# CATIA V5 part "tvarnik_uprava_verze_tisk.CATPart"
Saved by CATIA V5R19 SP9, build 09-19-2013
Part number: Part41.1
Bounding box of the stored display mesh (mm): x -57 to 50, y -37 to 37, z -20 to 10.351
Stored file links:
  C:\Users\jsmid\Desktop\DP_Smidak_Forma LEGO\tvarnik_uprava_verze_tisk.CATPart
  C:\Users\jsmid\Desktop\Forma_kostka\Product3.CATProduct
  C:\Users\jsmid\Desktop\DP_Smidak_Forma LEGO\LEGO_kostka.CATPart
  C:\Users\jsmid\Desktop\Forma_kostka\Babyplast_univ_ram_plus_LEGO_2.CATProduct
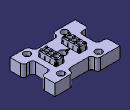
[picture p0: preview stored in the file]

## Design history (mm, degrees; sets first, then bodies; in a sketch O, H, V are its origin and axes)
Set1 "vtok"
  Point1: (0, 0, 0)
  Point2: (0, 0, 40)
  Point3: (0, 0, -7)
  Point4: (6.2, 0, -1.4)
  Point5: (8.8, 0, -0.58)
  Point6: (11.1, 0, -0.58)
  Point7: (-6.2, 0, -1.4)
  Point8: (-8.8, 0, -0.58)
  Point9: (-11.1, 0, -0.58)
  Line1: type PtPt, SecondPoint Point5, FirstPoint Point4
  Line2: type PtPt, SecondPoint Point6, FirstPoint Point5
  Line3: type PtPt, SecondPoint Point8, FirstPoint Point7
  Line4: type PtPt, SecondPoint Point9, FirstPoint Point8
  Point10: (0, 0, -1.4), relative to Point1
  Line5: type PtPt, SecondPoint Point10, FirstPoint Point2
  Line6: type PtPt, SecondPoint Point3, FirstPoint Point10
  Line7: type PtPt, SecondPoint Point7, FirstPoint Point10
  Line8: type PtPt, SecondPoint Point4, FirstPoint Point10
Set2
  DatumSurface1: linked copy from another document
  DatumSurface2: linked copy from another document
Body1 (main body)
  Sketch1 on xy-plane, origin (0, 0, 0), H (1, 0, 0), V (0, 1, 0)
    line L1 (-57, -37) -> (-0.0515, -37)
    line L2 (-0.0515, -37) -> (-0.0515, 37)
    line L3 (-0.0515, 37) -> (-57, 37)
    line L4 (-57, 37) -> (-57, -37)
    length L2 = 74
    distance H L3 = 37
    distance V L4 = 57
    horizontal: L1 H, L3 H
    vertical: L2 V, L4 V
  Pad1: profile Sketch1, direction (0, 0, 1), length 32
  AssyPrtSPLIT1: SplitPlane DatumSurface1
  Sketch2 on xy-plane, origin (0, 0, 0), H (1, 0, 0), V (0, 1, 0)
    line L1 (-0.0515, -37) -> (73, -37)
    line L2 (73, -37) -> (73, 37)
    line L3 (73, 37) -> (-0.0515, 37)
    line L4 (-0.0515, 37) -> (-0.0515, -37)
    length L2 = 74
    distance H L1 = 37
    distance V L2 = 73
    horizontal: L1 H, L3 H
    vertical: L2 V, L4 V
  Pad2: profile Sketch2, direction (0, 0, 1), length 32
  AssyPrtSPLIT2: SplitPlane DatumSurface2
  Sketch3 on xy-plane, origin (0, 0, 0), H (1, 0, 0), V (0, 1, 0)
    line L1 (-57, -37) -> (50, -37)
    line L2 (50, -37) -> (50, 37)
    line L3 (50, 37) -> (-57, 37)
    line L4 (-57, 37) -> (-57, -37)
    length L2 = 74
    distance H L1 = 37
    distance V L2 = 50
    distance L4 V = 57
    horizontal: L1 H, L3 H
    vertical: L2 V, L4 V
  Pad3: profile Sketch3, direction (0, 0, -1), length 20.027
  DatumCurve1 to DatumCurve8
  Sketch4 on start face of Pad3, origin (0, 0, 0), H (1, 0, 0), V (0, 1, 0)
  Sketch5 on face of AssyPrtSPLIT2, origin (0, 0, 8.643), H (1, 0, 0), V (0, 1, 0)
    circle A1 centre (18.939, -8.04) radius 2.25
    reference projected arc E1 centre (18.939, -8.04) radius 2.25 from (18.939, -10.29) to (18.939, -5.79) ccw from edge [start face of Pad3 | face of AssyPrtSPLIT2]
    circle A2 centre (18.939, 0) radius 2.6
    point P2 (18.939, 0)
    circle A3 centre (18.939, 8.04) radius 2.25
    reference projected arc E2 centre (18.939, 8.04) radius 2.25 from (18.939, 5.79) to (18.939, 10.29) ccw from edge [start face of Pad3 | face of AssyPrtSPLIT2]
    circle A4 centre (-18.939, -8.04) radius 2.25
    circle A5 centre (-18.939, 0) radius 2.6
    circle A6 centre (-18.939, 8.04) radius 2.25
    radius A1 = 2.25
    distance E1 A1 = 0
    radius A2 = 2.6
    distance A3 E2 = 0
    radius A3 = 2.25
    coincidence: P2 H
    symmetry: A1 A4 V, A2 A5 V, A3 A6 V
  Pocket1: profile Sketch5, direction (0, 0, -1), up to xy-plane
  Sketch6 on face of AssyPrtSPLIT2, origin (0, 0, 8.643), H (1, 0, 0), V (0, 1, 0)
    circle A1 centre (18.939, -8.04) radius 2.25
    point P1 (18.939, -8.04)
    reference projected arc E1 centre (18.939, -8.04) radius 2.25 from (18.939, -10.29) to (18.939, -5.79) ccw from edge [start face of Pad3 | face of AssyPrtSPLIT2]
    circle A2 centre (18.939, 0) radius 2.25
    point P2 (18.939, 0)
    circle A3 centre (18.939, 8.04) radius 2.25
    reference projected arc E2 centre (18.939, 8.04) radius 2.25 from (18.939, 5.79) to (18.939, 10.29) ccw from edge [start face of Pad3 | face of AssyPrtSPLIT2]
    circle A4 centre (-18.939, -8.04) radius 2.25
    circle A5 centre (-18.939, 0) radius 2.25
    circle A6 centre (-18.939, 8.04) radius 2.25
    radius A1 = 2.25
    distance E1 A1 = 0
    radius A2 = 2.25
    distance A3 E2 = 0
    radius A3 = 2.25
    distance P1 P2 = 8.04
    coincidence: P2 H
    symmetry: A1 A4 V, A2 A5 V, A3 A6 V
  Pocket2: profile Sketch6, direction (0, 0, -1), through (limit type 6)
  Sketch7 on start face of Pad3, origin (0, 0, 0), H (1, 0, 0), V (0, 1, 0)
    circle A1 centre (18.939, 0) radius 2.3
    point P1 (18.939, 0)
    reference projected circle E1 centre (18.939, 0) radius 2.25 from Sketch6.A2
    circle A2 centre (18.939, 8.04) radius 2.3
    reference projected circle E2 centre (18.939, 8.04) radius 2.25 from Sketch6.A3
    circle A3 centre (18.939, -8.04) radius 2.3
    reference projected circle E3 centre (18.939, -8.04) radius 2.25 from Sketch6.A1
    radius A1 = 2.3
    distance A1 E1 = 0.05
    radius A2 = 2.3
    distance A2 E2 = 0.05
    radius A3 = 2.3
    distance A3 E3 = 0.05
    coincidence: P1 H
  Pocket3: profile Sketch7, direction (0, 0, -1), through (limit type 6)
  Mirror1: of Pocket3, about yz-plane
  Sketch8 on end face of Pad3, origin (0, 0, -20.027), H (1, 0, 0), V (0, -1, 0)
    line L1 (70.9433, 55.9375) -> (70.9433, -55.9375)
    line L2 (70.9433, -55.9375) -> (-70.9433, -55.9375)
    line L3 (-70.9433, -55.9375) -> (-70.9433, 55.9375)
    line L4 (-70.9433, 55.9375) -> (70.9433, 55.9375)
    vertical: L1 V, L3 V
    horizontal: L2 H, L4 H
    equidistance: L1 L3 O, L2 L4 O
  Pocket4: profile Sketch8, direction (0, 0, 1), length 0.027
  Sketch9 on start face of Pad3, origin (0, 0, 0), H (1, 0, 0), V (0, 1, 0)
    circle A1 centre (0, 0) radius 6
    radius A1 = 6
  Pocket5: profile Sketch9, direction (0, 0, -1), length 14
  Sketch10 on end face of Pocket4, origin (0, 0, -20), H (1, 0, 0), V (0, -1, 0)
    circle A1 centre (0, 0) radius 8
    radius A1 = 8
  Pocket6: profile Sketch10, direction (0, 0, 1), length 6
  Sketch11 on end face of Pocket4, origin (0, 0, -20), H (1, 0, 0), V (0, -1, 0)
    construction line L1 (0, 5.5011) -> (0, 12.5011)
    point P1 (0, 5.5011)
    line L2 (-2, 5.5011) -> (-2, 12.5011)
    line L3 (2, 12.5011) -> (2, 5.5011)
    arc A1 centre (0, 12.5011) radius 2 from (-2, 12.5011) to (2, 12.5011) cw
    arc A2 centre (0, 5.5011) radius 2 from (2, 5.5011) to (-2, 5.5011) cw
    distance L1 L2 = 2
    length L1 = 7
    coincidence: P1 V
    vertical: L1 V
    tangency: A1 L2, A2 L2, A1 L3, A2 L3
  Pocket7: profile Sketch11, direction (0, 0, 1), length 5
  DatumCurve9
  DatumSurface3 to DatumSurface5
  Sketch12 on start face of Pad3, origin (0, 0, 0), H (1, 0, 0), V (0, 1, 0)
    point P1 (42.5, 0)
    line L1 (50, 15) -> (50, -15)
    line L2 (50, -15) -> (35, -15)
    line L3 (35, -15) -> (35, 15)
    line L4 (35, 15) -> (50, 15)
    reference projected line E1 (50, -37) -> (50, 37) from edge [face of Pad3 from Sketch3.L2 | start face of Pad3]
    point P6 (-49.5, 0)
    line L5 (-42, 15) -> (-42, -15)
    line L6 (-42, -15) -> (-57, -15)
    line L7 (-57, -15) -> (-57, 15)
    line L8 (-57, 15) -> (-42, 15)
    reference projected line E2 (-57, 37) -> (-57, -37) from edge [face of Pad3 from Sketch3.L4 | start face of Pad3]
    point P11 (0, -32)
    line L9 (20, -27) -> (20, -37)
    line L10 (20, -37) -> (-20, -37)
    line L11 (-20, -37) -> (-20, -27)
    line L12 (-20, -27) -> (20, -27)
    reference projected line E3 (-57, -37) -> (55, -37) from edge [face of Pad3 from Sketch3.L1 | start face of Pad3]
    point P16 (0, 32)
    line L13 (20, 37) -> (20, 27)
    line L14 (20, 27) -> (-20, 27)
    line L15 (-20, 27) -> (-20, 37)
    line L16 (-20, 37) -> (20, 37)
    reference projected line E4 (55, 37) -> (-57, 37) from edge [face of Pad3 from Sketch3.L3 | start face of Pad3]
    distance L1 E1 = 0
    length L4 = 15
    length L3 = 30
    distance L7 E2 = 0
    length L5 = 30
    length L6 = 15
    distance L10 E3 = 0
    length L9 = 10
    length L12 = 40
    distance L16 E4 = 0
    length L14 = 40
    length L13 = 10
    coincidence: P1 H, P6 H, P11 V, P16 V
    vertical: L1 V, L3 V, L5 V, L7 V, L9 V, L11 V, L13 V, L15 V
    horizontal: L2 H, L4 H, L6 H, L8 H, L10 H, L12 H, L14 H, L16 H
    equidistance: L1 L3 P1, L2 L4 P1, L5 L7 P6, L6 L8 P6, L9 L11 P11, L10 L12 P11, L13 L15 P16, L14 L16 P16
  Pocket8: profile Sketch12, direction (0, 0, -1), through (limit type 6)
  DatumCurve10
  DatumCurve11
  DatumPoint1
  Sketch13 on start face of Pad3, origin (0, 0, 0), H (1, 0, 0), V (0, 1, 0)
    point P1 (12.0055, 0)
    reference projected line E1 (12.2055, 3.7185) -> (12.2055, -3.7185) from edge [start face of Pad3 | face of AssyPrtSPLIT2]
    distance P1 E1 = 0.2
    coincidence: P1 H
  Sketch14 on face of Pad3, origin (0, 0, 0), H (1, 0, 0), V (0, 1, 0)
    point P1 (18.9406, 0)
    line L1 (22.2198, 10.6951) -> (22.2198, -10.6951)
    line L2 (22.2198, -10.6951) -> (15.6614, -10.6951)
    line L3 (15.6614, -10.6951) -> (15.6614, 10.6951)
    line L4 (15.6614, 10.6951) -> (22.2198, 10.6951)
    point P6 (-19.035, 0)
    line L5 (-15.5945, 11.234) -> (-15.5945, -11.234)
    line L6 (-15.5945, -11.234) -> (-22.4754, -11.234)
    line L7 (-22.4754, -11.234) -> (-22.4754, 11.234)
    line L8 (-22.4754, 11.234) -> (-15.5945, 11.234)
    coincidence: P1 H, P6 H
    vertical: L1 V, L3 V, L5 V, L7 V
    horizontal: L2 H, L4 H, L6 H, L8 H
    equidistance: L1 L3 P1, L2 L4 P1, L5 L7 P6, L6 L8 P6
  Pad4: profile Sketch14, direction (0, 0, -1), length 20
  Sketch15 on face of Pad4, origin (0, 0, 0), H (1, 0, 0), V (0, 1, 0)
    circle A1 centre (18.939, 0) radius 2.25
    point P1 (18.939, 0)
    reference projected circle E1 centre (18.939, 0) radius 2.3 from Sketch7.A1
    circle A2 centre (18.939, 8.04) radius 2.25
    reference projected circle E2 centre (18.939, 8.04) radius 2.3 from Sketch7.A2
    circle A3 centre (18.939, -8.04) radius 2.25
    reference projected circle E3 centre (18.939, -8.04) radius 2.3 from Sketch7.A3
    radius A1 = 2.25
    distance A1 E1 = 0.05
    radius A2 = 2.25
    distance A2 E2 = 0.05
    radius A3 = 2.25
    distance A3 E3 = 0.05
    coincidence: P1 H
  Pocket9: profile Sketch15, direction (0, 0, -1), through (limit type 6)
  DatumSurface6
  Mirror2: of Pocket9, about yz-plane
  AssyPrtSPLIT3: SplitPlane DatumSurface6
  Sketch16 on face of AssyPrtSPLIT3, origin (0, 0, 0), H (1, 0, 0), V (0, 1, 0)
    projected line E1 (-6.1651, -1.8927) -> (-7.8487, -1.4415) from edge [face of AssyPrtSPLIT3 | face of AssyPrtSPLIT3]
    projected arc E2 centre (-7.4607, 0.0063) radius 1.499 from (-8.4621, -1.1091) to (-7.8487, -1.4415) ccw from edge [face of AssyPrtSPLIT3 | face of AssyPrtSPLIT3]
    projected line E3 (-6.1651, 1.9073) -> (-6.1651, -1.8927) from edge [face of AssyPrtSPLIT3 | face of AssyPrtSPLIT3]
    projected line E4 (-6.1651, 1.9073) -> (-7.8487, 1.4562) from edge [face of AssyPrtSPLIT3 | face of AssyPrtSPLIT3]
    projected arc E5 centre (-7.4607, 0.0084) radius 1.499 from (-7.8487, 1.4562) to (-8.4621, 1.1238) ccw from edge [face of AssyPrtSPLIT3 | face of AssyPrtSPLIT3]
    projected arc E6 centre (-8.7635, 1.4556) radius 0.4483 from (-8.7574, 1.0074) to (-8.4621, 1.1238) ccw from edge [face of AssyPrtSPLIT3 | face of AssyPrtSPLIT3]
    projected line E7 (-8.7574, 1.0073) -> (-11.1897, 1.0074) from edge [face of AssyPrtSPLIT3 | face of AssyPrtSPLIT3]
    projected arc E8 centre (-8.7622, -1.4376) radius 0.445 from (-8.4621, -1.1091) to (-8.7574, -0.9926) ccw from edge [face of AssyPrtSPLIT3 | face of AssyPrtSPLIT3]
    projected line E9 (-11.1897, -0.9927) -> (-8.7574, -0.9926) from edge [face of AssyPrtSPLIT3 | face of AssyPrtSPLIT3]
    projected curve E10 from edge [face of AssyPrtSPLIT3 | face of AssyPrtSPLIT3]
    projected curve E11 from edge [face of AssyPrtSPLIT3 | face of AssyPrtSPLIT3]
    projected line E12 (-12.1595, 0.0186) -> (-12.1595, -0.0039) from edge [face of AssyPrtSPLIT3 | face of AssyPrtSPLIT3]
    line L1 (1.0844, -8.2304) -> (-12.2055, -8.2304)
    line L2 (-12.2055, -8.2304) -> (-12.2055, 7.0998)
    line L3 (-12.2055, 7.0998) -> (1.0844, 7.0998)
    line L4 (1.0844, 7.0998) -> (1.0844, -8.2304)
    reference projected line E13 (-12.2055, -3.7185) -> (-12.2055, 3.7185) from edge [face of AssyPrtSPLIT3 | face of AssyPrtSPLIT1]
    horizontal: L1 H, L3 H
    vertical: L2 V, L4 V
    coincidence: L2 E13
  Pad5: profile Sketch16, direction (0, 0, -1), length 1
  Sketch17 on face of Pad5, origin (0, 0, 0), H (1, 0, 0), V (0, 1, 0)
    circle A1 centre (0, 0) radius 6
    reference projected circle E1 centre (0, 0) radius 6 from edge [face of Pad5 | face of Pocket5 from Sketch9.A1]
    tangency: A1 E1
  Pocket10: profile Sketch17, direction (0, 0, -1), through (limit type 6), offset 1
  DatumSurface7
  Sketch18 on face of Pad5, origin (-6.1651, 0, 0), H (0, -1, 0), V (0, 0, 1)
  Pocket11: profile Sketch18, direction (1, 0, 0), through (limit type 6)
  AssyPrtSPLIT4: SplitPlane DatumSurface7
  Sketch19 on face of AssyPrtSPLIT4, origin (0, 0, 0), H (1, 0, 0), V (0, 1, 0)
    projected line E1 (8.7574, -1.0073) -> (11.1897, -1.0074) from edge [face of AssyPrtSPLIT4 | face of AssyPrtSPLIT4]
    projected line E2 (6.1651, -1.9073) -> (7.8487, -1.4562) from edge [face of AssyPrtSPLIT4 | face of AssyPrtSPLIT4]
    projected arc E3 centre (7.4607, -0.0084) radius 1.499 from (7.8487, -1.4562) to (8.4621, -1.1238) ccw from edge [face of AssyPrtSPLIT4 | face of AssyPrtSPLIT4]
    projected arc E4 centre (8.7635, -1.4556) radius 0.4483 from (8.7574, -1.0073) to (8.4621, -1.1238) ccw from edge [face of AssyPrtSPLIT4 | face of AssyPrtSPLIT4]
    projected curve E5 from edge [face of AssyPrtSPLIT4 | face of AssyPrtSPLIT4]
    projected curve E6 from edge [face of AssyPrtSPLIT4 | face of AssyPrtSPLIT4]
    projected line E7 (11.1897, 0.9927) -> (8.7574, 0.9926) from edge [face of AssyPrtSPLIT4 | face of AssyPrtSPLIT4]
    projected arc E8 centre (8.7622, 1.4376) radius 0.445 from (8.4621, 1.1091) to (8.7574, 0.9926) ccw from edge [face of AssyPrtSPLIT4 | face of AssyPrtSPLIT4]
    projected arc E9 centre (7.4607, -0.0063) radius 1.499 from (8.4621, 1.1091) to (7.8487, 1.4415) ccw from edge [face of AssyPrtSPLIT4 | face of AssyPrtSPLIT4]
    projected line E10 (6.1651, 1.8927) -> (7.8487, 1.4415) from edge [face of AssyPrtSPLIT4 | face of AssyPrtSPLIT4]
    projected line E11 (6.1651, -1.9073) -> (6.1651, 1.8927) from edge [face of AssyPrtSPLIT4 | face of AssyPrtSPLIT4]
    line L1 (2.0371, -7.0751) -> (12.2055, -7.0751)
    line L2 (12.2055, -7.0751) -> (12.2055, 6.9763)
    line L3 (12.2055, 6.9763) -> (2.0371, 6.9763)
    line L4 (2.0371, 6.9763) -> (2.0371, -7.0751)
    reference projected line E12 (12.2055, 3.7185) -> (12.2055, -3.7185) from edge [face of AssyPrtSPLIT4 | face of AssyPrtSPLIT2]
    projected line E13 (12.1595, -0.0186) -> (12.1595, 0.0039) from edge [face of AssyPrtSPLIT4 | face of AssyPrtSPLIT4]
    horizontal: L1 H, L3 H
    vertical: L2 V, L4 V
    coincidence: L2 E12
  Pad6: profile Sketch19, direction (0, 0, -1), length 1
  Sketch20 on face of Pad6, origin (0, 0, 0), H (1, 0, 0), V (0, 1, 0)
    circle A1 centre (0, 0) radius 6
    reference projected arc E1 centre (0, 0) radius 6 from (-5.6937, -1.8927) to (4.3696, -4.1118) ccw from edge [face of AssyPrtSPLIT4 | face of Pocket5]
    tangency: A1 E1
  Pocket12: profile Sketch20, direction (0, 0, -1), length 1
  Sketch21 on face of Pad6, origin (6.1651, 0, 0), H (0, 1, 0), V (0, 0, 1)
  Pocket13: profile Sketch21, direction (-1, 0, 0), length 1
  DatumCurve12
  DatumSurface8
  Sketch22 on face of Pad4, origin (0, 0, -20), H (1, 0, 0), V (0, -1, 0)
    circle A1 centre (-31, 28) radius 3.25
    point P1 (-31, 28)
    circle A2 centre (31, 28) radius 3.25
    point P2 (31, 28)
    circle A3 centre (31, -28) radius 3.25
    point P3 (31, -28)
    circle A4 centre (-31, -28) radius 3.25
    point P4 (-31, -28)
    radius A1 = 3.25
    distance V P1 = 31
    distance H P1 = 28
    distance P2 V = 31
    distance H P2 = 28
    radius A2 = 3.25
    radius A3 = 3.25
    distance H P3 = 28
    distance P3 V = 31
    radius A4 = 3.25
    distance P4 V = 31
    distance P4 H = 28
  Pocket14: profile Sketch22, direction (0, 0, -1), through (limit type 6)
  Sketch23 on face of Pad6, origin (0, 0, 0), H (1, 0, 0), V (0, 1, 0)
    circle A1 centre (-31, -28) radius 5.5
    point P1 (-31, -28)
    circle A2 centre (31, -28) radius 5.5
    point P2 (31, -28)
    circle A3 centre (31, 28) radius 5.5
    point P3 (31, 28)
    circle A4 centre (-31, 28) radius 5.5
    point P4 (-31, 28)
    radius A1 = 5.5
    distance P1 V = 31
    distance H P1 = 28
    radius A2 = 5.5
    distance P2 V = 31
    distance P2 H = 28
    radius A3 = 5.5
    distance V P3 = 31
    distance H P3 = 28
    radius A4 = 5.5
    distance P4 V = 31
    distance H P4 = 28
  Pocket15: profile Sketch23, direction (0, 0, -1), length 7
  Fillet1: radius 5, on edge [face of Pocket8 from Sketch12.L11 | face of Pocket8 from Sketch12.L12]; edge [face of Pad3 from Sketch3.L1 | face of Pocket8 from Sketch12.L11]; edge [face of Pocket8 from Sketch12.L12 | face of Pocket8 from Sketch12.L9]; edge [face of Pocket8 from Sketch12.L9 | face of Pad3 from Sketch3.L1]; edge [face of Pocket8 from Sketch12.L13 | face of Pocket8 from Sketch12.L14]; edge [face of Pad3 from Sketch3.L3 | face of Pocket8 from Sketch12.L13]; edge [face of Pocket8 from Sketch12.L14 | face of Pocket8 from Sketch12.L15]; edge [face of Pocket8 from Sketch12.L15 | face of Pad3 from Sketch3.L3]
  Fillet2: radius 5, on edge [face of Pocket8 from Sketch12.L3 | face of Pocket8 from Sketch12.L4]; edge [face of Pocket8 from Sketch12.L4 | face of Pad3 from Sketch3.L2]; edge [face of Pocket8 from Sketch12.L2 | face of Pocket8 from Sketch12.L3]; edge [face of Pad3 from Sketch3.L2 | face of Pocket8 from Sketch12.L2]
  Fillet3: radius 5, on edge [face of Pocket8 from Sketch12.L5 | face of Pocket8 from Sketch12.L6]; edge [face of Pocket8 from Sketch12.L8 | face of Pocket8 from Sketch12.L5]; edge [face of Pad3 from Sketch3.L4 | face of Pocket8 from Sketch12.L8]; edge [face of Pocket8 from Sketch12.L6 | face of Pad3 from Sketch3.L4]
  Sketch24 on face of AssyPrtSPLIT1, origin (0, 0, 2.3115), H (1, 0, 0), V (0, 1, 0)
    line L1 (-25.9963, -0.7064) -> (-21.8328, -0.7064)
    line L2 (-21.8328, -0.7064) -> (-21.8328, 0.6745)
    line L3 (-21.8328, 0.6745) -> (-25.9963, 0.6745)
    line L4 (-25.9963, 0.6745) -> (-25.9963, -0.7064)
    point P5 (-16.1431, -0.7064)
    line L5 (-16.1431, -0.7064) -> (-11.9819, -0.7064)
    line L6 (-11.9819, -0.7064) -> (-11.9819, 0.7687)
    line L7 (-11.9819, 0.7687) -> (-16.1431, 0.7687)
    line L8 (-16.1431, 0.7687) -> (-16.1431, -0.7064)
    point P9 (11.6606, -0.7064)
    line L9 (11.6606, -0.7064) -> (16.1367, -0.7064)
    line L10 (16.1367, -0.7064) -> (16.1367, 0.7687)
    line L11 (16.1367, 0.7687) -> (11.6606, 0.7687)
    line L12 (11.6606, 0.7687) -> (11.6606, -0.7064)
    point P11 (16.1367, 0.7687)
    point P13 (21.5854, -0.7064)
    line L13 (21.5854, -0.7064) -> (26.1561, -0.7064)
    line L14 (26.1561, -0.7064) -> (26.1561, 0.7687)
    line L15 (26.1561, 0.7687) -> (21.5854, 0.7687)
    line L16 (21.5854, 0.7687) -> (21.5854, -0.7064)
    point P15 (26.1561, 0.7687)
    horizontal: L1 H, L3 H, L5 H, L7 H, L9 H, L11 H, L13 H, L15 H
    vertical: L2 V, L4 V, L6 V, L8 V, L10 V, L12 V, L14 V, L16 V
    coincidence: P5 L1, P9 L5, P11 L7, P13 L9, P15 L11
  Pad7: profile Sketch24, direction (0, 0, 1), length 7
  Sketch25 on face of Pad4, origin (0, 0, 0), H (1, 0, 0), V (0, 1, 0)
    circle A1 centre (18.939, 0) radius 3.2712
    point P1 (18.939, 0)
    reference projected arc E1 centre (18.9389, 0) radius 3.2713 from (18.939, -3.2713) to (18.939, 3.2713) ccw from edge [face of Pad4 | face of AssyPrtSPLIT2]
    reference projected arc E2 centre (18.9391, 0) radius 3.2713 from (18.939, 3.2713) to (18.939, -3.2713) ccw from edge [face of Pad4 | face of AssyPrtSPLIT2]
    distance E2 A1 = 0
    coincidence: P1 H
    tangency: A1 E1
  Sketch26 on face of AssyPrtSPLIT1, origin (0, 0, 8.643), H (1, 0, 0), V (0, 1, 0)
    circle A1 centre (18.9034, 0) radius 3.4578
    point P1 (18.9034, 0)
    reference projected arc E1 centre (18.939, 0) radius 3.4221 from (18.939, -3.4221) to (22.3225, -0.5125) ccw from edge [face of AssyPrtSPLIT2 | face of AssyPrtSPLIT2]
    reference projected arc E2 centre (18.939, 0) radius 3.4221 from (18.939, 3.4221) to (15.5555, 0.5125) ccw from edge [face of AssyPrtSPLIT2 | face of AssyPrtSPLIT2]
    distance A1 E2 = 0
    coincidence: P1 H
    tangency: A1 E1
  Loft1: solid, Sections (Sketch25; Sketch26)
  Sketch27 on face of Pad4, origin (0, 0, 0), H (1, 0, 0), V (0, 1, 0)
    circle A1 centre (-18.939, 0) radius 3.2712
    point P1 (-18.939, 0)
    reference projected arc E1 centre (-18.9391, 0) radius 3.2713 from (-18.939, -3.2713) to (-18.939, 3.2713) ccw from edge [face of Pad4 | face of AssyPrtSPLIT1]
    reference projected arc E2 centre (-18.9389, 0) radius 3.2713 from (-18.939, 3.2713) to (-18.939, -3.2713) ccw from edge [face of Pad4 | face of AssyPrtSPLIT1]
    distance A1 E2 = 0
    coincidence: P1 H
    tangency: A1 E1
  Sketch28 on face of AssyPrtSPLIT1, origin (0, 0, 8.643), H (1, 0, 0), V (0, 1, 0)
    circle A1 centre (-18.939, 0) radius 3.4221
    point P1 (-18.939, 0)
    reference projected arc E1 centre (-18.939, 0) radius 3.4221 from (-15.5555, 0.5125) to (-18.939, 3.4221) ccw from edge [face of AssyPrtSPLIT1 | face of AssyPrtSPLIT1]
    reference projected arc E2 centre (-18.939, 0) radius 3.4221 from (-22.3225, -0.5125) to (-18.939, -3.4221) ccw from edge [face of AssyPrtSPLIT1 | face of AssyPrtSPLIT1]
    coincidence: P1 H, A1 E2
    tangency: A1 E1
  Loft2: solid, Sections (Sketch27; Sketch28)
  Sketch29 on face of Pad7 from Sketch24.L13, origin (0, -0.7064, 0), H (1, 0, 0), V (0, 0, 1)
    line L1 (25.6389, 1.926) -> (27.1983, 1.926)
    line L2 (27.1983, 1.926) -> (27.1983, 9.8187)
    line L3 (27.1983, 9.8187) -> (20.765, 9.8187)
    line L4 (20.765, 9.8187) -> (20.765, 8.643)
    line L5 (20.765, 8.643) -> (25.5216, 8.643)
    point P6 (25.5216, 8.643)
    reference projected line E1 (25.5216, 8.643) -> (22.2874, 8.643) from edge [face of Pad7 from Sketch24.L13 | face of AssyPrtSPLIT2]
    reference projected point E2 (25.5216, 8.643) from edge [face of AssyPrtSPLIT2 | face of AssyPrtSPLIT2]
    line L6 (25.5216, 8.643) -> (25.6389, 1.926)
    reference projected line E3 (25.5216, 8.643) -> (25.6322, 2.3115) from edge [face of AssyPrtSPLIT2 | face of Pad7 from Sketch24.L13]
    line L7 (11.4606, 1.6133) -> (12.2337, 1.6133)
    line L8 (12.2337, 1.6133) -> (12.3564, 8.643)
    point P9 (12.3564, 8.643)
    line L9 (12.3564, 8.643) -> (16.4286, 8.643)
    line L10 (16.4286, 8.643) -> (16.4286, 10.1158)
    line L11 (16.4286, 10.1158) -> (11.4606, 10.1158)
    line L12 (11.4606, 10.1158) -> (11.4606, 1.6133)
    reference projected line E4 (12.3564, 8.643) -> (12.2458, 2.3115) from edge [face of Pad7 from Sketch24.L9 | face of AssyPrtSPLIT2]
    reference projected line E5 (12.3564, 8.643) -> (15.5906, 8.643) from edge [face of AssyPrtSPLIT2 | face of Pad7 from Sketch24.L9]
    reference projected point E6 (12.3564, 8.643) from edge [face of AssyPrtSPLIT2 | face of AssyPrtSPLIT2]
    horizontal: L1 H, L3 H, L5 H, L7 H, L9 H, L11 H
    vertical: L2 V, L4 V, L10 V, L12 V
    coincidence: L5 E1, P6 E2, L6 E3, L8 E4, L9 E5, P9 E6
  Pocket16: profile Sketch29, direction (0, 1, 0), length 2
  Sketch30 on face of Pad7 from Sketch24.L5, origin (0, -0.7064, 0), H (1, 0, 0), V (0, 0, 1)
    line L1 (-11.5471, 2.0062) -> (-12.2405, 2.0062)
    line L2 (-12.2405, 2.0062) -> (-12.3564, 8.643)
    point P3 (-12.3564, 8.643)
    line L3 (-12.3564, 8.643) -> (-17.2941, 8.643)
    line L4 (-17.2941, 8.643) -> (-17.2941, 10.4435)
    line L5 (-17.2941, 10.4435) -> (-10.6128, 10.4435)
    line L6 (-10.6128, 10.4435) -> (-11.5471, 2.0062)
    reference projected line E1 (-12.3564, 8.643) -> (-12.2458, 2.3115) from edge [face of AssyPrtSPLIT1 | face of Pad7 from Sketch24.L5]
    reference projected line E2 (-12.3564, 8.643) -> (-15.5906, 8.643) from edge [face of Pad7 from Sketch24.L5 | face of AssyPrtSPLIT1]
    reference projected point E3 (-12.3564, 8.643) from edge [face of AssyPrtSPLIT1 | face of AssyPrtSPLIT1]
    line L7 (-26.6543, 1.8146) -> (-25.6408, 1.8146)
    line L8 (-25.6408, 1.8146) -> (-25.5216, 8.643)
    point P9 (-25.5216, 8.643)
    line L9 (-25.5216, 8.643) -> (-21.386, 8.643)
    line L10 (-21.386, 8.643) -> (-21.386, 9.7194)
    line L11 (-21.386, 9.7194) -> (-27.226, 9.7194)
    line L12 (-27.226, 9.7194) -> (-26.6543, 1.8146)
    reference projected line E4 (-25.5216, 8.643) -> (-25.6322, 2.3115) from edge [face of Pad7 from Sketch24.L1 | face of AssyPrtSPLIT1]
    reference projected line E5 (-25.5216, 8.643) -> (-22.2874, 8.643) from edge [face of AssyPrtSPLIT1 | face of Pad7 from Sketch24.L1]
    reference projected point E6 (-25.5216, 8.643) from edge [face of AssyPrtSPLIT1 | face of AssyPrtSPLIT1]
    horizontal: L1 H, L3 H, L5 H, L7 H, L9 H, L11 H
    vertical: L4 V, L10 V
    coincidence: L2 E1, L3 E2, P3 E3, L8 E4, L9 E5, P9 E6
  Pocket17: profile Sketch30, direction (0, 1, 0), length 2
  Draft1: Angle 3, SupportToDraft (face of AssyPrtSPLIT2; face of AssyPrtSPLIT2; face of Pocket16; face of AssyPrtSPLIT2; face of AssyPrtSPLIT2; face of AssyPrtSPLIT2; face of AssyPrtSPLIT2; face of AssyPrtSPLIT2; face of AssyPrtSPLIT2; face of AssyPrtSPLIT2; face of Pocket16; face of AssyPrtSPLIT2; face of AssyPrtSPLIT2; face of AssyPrtSPLIT2; face of AssyPrtSPLIT2; face of AssyPrtSPLIT2), PullDir (0, 0, 1), Neutral face of Pad6
  Draft2: Angle 3, SupportToDraft (face of AssyPrtSPLIT1; face of AssyPrtSPLIT1; face of AssyPrtSPLIT1; face of AssyPrtSPLIT1; face of AssyPrtSPLIT1; face of Pocket17; face of AssyPrtSPLIT1; face of AssyPrtSPLIT1; face of AssyPrtSPLIT1; face of AssyPrtSPLIT1; face of AssyPrtSPLIT1; face of AssyPrtSPLIT1; face of AssyPrtSPLIT1; face of Pocket17; face of AssyPrtSPLIT1; face of AssyPrtSPLIT1), PullDir (0, 0, 1), Neutral face of Pad6
  Fillet4: radius 0.5, on edge [face of AssyPrtSPLIT2 | face of AssyPrtSPLIT2] (x4); edge [face of AssyPrtSPLIT1 | face of AssyPrtSPLIT1] (x4)
  Draft3: Angle 2, SupportToDraft (face of AssyPrtSPLIT1; face of Loft2; face of AssyPrtSPLIT1; face of AssyPrtSPLIT2; face of Loft1; face of AssyPrtSPLIT2), PullDir face of Pocket17, Neutral face of Pad4
  Chamfer1: length 1, angle 45, on face of Pad4
  Thickness1: Face (end face of Pocket6; end face of Pocket7), Thickness -1
  Chamfer2: length 0.5, angle 45, on edge [end face of Pocket6 | face of Pocket12]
